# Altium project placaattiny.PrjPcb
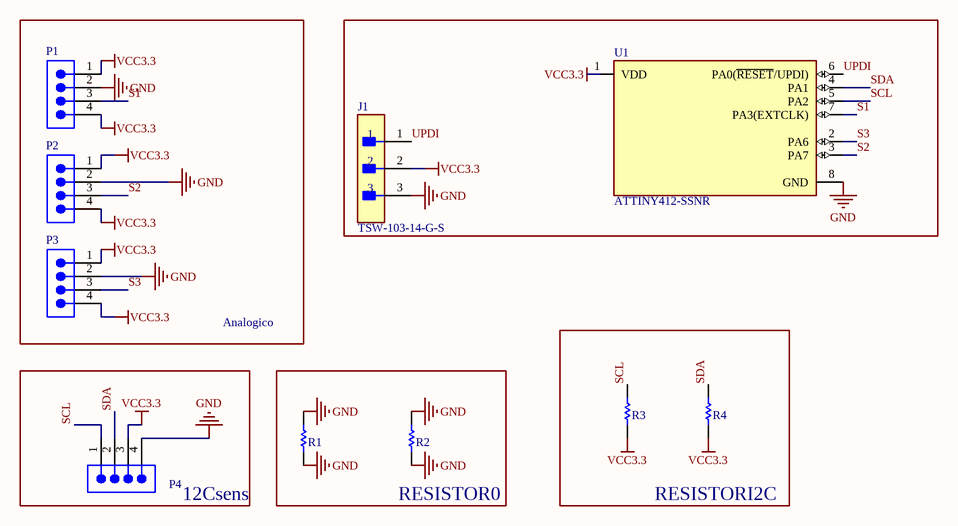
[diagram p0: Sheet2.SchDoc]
1 sheet, 10 parts. Net scope: global (net labels, ports and power ports of the same name join across sheets).
Board file: PCB2.PcbDoc

## Sheet Sheet2.SchDoc
size A4; SheetNumber: 1; SheetTotal: 1

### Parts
J1  TSW-103-14-G-S  [FP-TSW-103-14-G-S-MFG]
P1  TSW-104-08-G-S  [SMTC-TSW-104-08-X-S]  (value not drawn)
P2  TSW-104-08-G-S  [SMTC-TSW-104-08-X-S]  (value not drawn)
P3  TSW-104-08-G-S  [SMTC-TSW-104-08-X-S]  (value not drawn)
P4  TSW-104-08-G-S  [SMTC-TSW-104-08-X-S]  (value not drawn)
R1  RC1206FR-076R98L  [RESC3116X65X40NL10T20]  (value not drawn)
R2  RC1206FR-076R98L  [RESC3116X65X40NL10T20]  (value not drawn)
R3  RC1206FR-10750RL  [RESC3116X65X40LL10T20]  (value not drawn)
R4  RC1206FR-10750RL  [RESC3116X65X40LL10T20]  (value not drawn)
U1  ATTINY412-SSNR  [FP-C04-057-SN-MFG]

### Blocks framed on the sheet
Analogico: P1-P3
RESISTORI2C: R3 R4
12Csens: P4
RESISTOR0: R1 R2

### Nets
GND: J1.3 P1.2 P2.2 P3.2 P4.4 R1.1 R1.2 R2.1 R2.2 U1.8(GND)
VCC3.3: J1.2 P1.1 P1.4 P2.1 P2.4 P3.1 P3.4 P4.3 R3.1 R4.1 U1.1(VDD)
S1: P1.3 U1.7(PA3(EXTCLK))
S2: P2.3 U1.3(PA7)
S3: P3.3 U1.2(PA6)
SCL: P4.1 R3.2 U1.5(PA2)
SDA: P4.2 R4.2 U1.4(PA1)
UPDI: J1.1 U1.6(PA0(~{RESET}/UPDI))

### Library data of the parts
J1 = CMP-02766-001743-1: CONN HEADER VERT 3POS 2.54MM; Max Voltage Rating (AC): 550V; Number of Positions: 3; Max Current Rating: 7.6A; Gender: Male
P1-P4 = CMP-1024-00357-1: 0.025" SQ Post Header, Through-hole, Vertical, -55 to 125 degC, 2.54 mm Pitch, 4-Pin, Male, RoHS; Manufacturer: Samtec; Pitch: 2.54 mm
R1 R2 = CMP-2003-03854-1: Manufacturer: Yageo
R3 R4 = CMP-2003-04964-1: Manufacturer: Yageo
U1 = CMP-06276-000158-1: IC MCU 8BIT 4KB FLASH 8SOIC; Peripherals: Brown-out Detect/Reset; Number of I/Os: 6; Core Architecture: AVR; Oscillator Type: Internal; Interface: I2C; Frequency: 20MHz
